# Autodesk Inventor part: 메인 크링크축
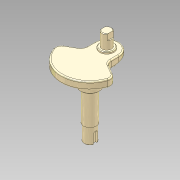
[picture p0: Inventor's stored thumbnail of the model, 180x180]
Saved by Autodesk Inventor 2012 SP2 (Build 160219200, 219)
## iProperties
Manager: KYOUNG IL JANG
Company: 한국ATC센터
Created: 2012-10
Part Number: 메인 크링크축
Document SubType Name: Modeling
Density: 1 g/cm^3
Checked By: KYOUNG IL JANG
Vendor: CBT Solutions
Designer: KYOUNG IL JANG
Material: 기본값
크링크폭: 19.000 mm
크랭크길이: 18.000 mm
크랭키위치: 65.000 mm
무게추: 90.000 mm
크랭크각도높이: 21.000 mm
크링크각도: -15.00 deg
Author: KYOUNG IL JANG
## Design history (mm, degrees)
sketch "스케치1"
  geometry: L1 (-19, 109.368)-(-19, 91.368); L2 (-19, 91.368)-(-44.545, 76.619); L3 (19, 109.368)-(19, 91.368); L4 (19, 91.368)-(44.545, 76.619); C1 r 32.5 at (0, 83) reference; C2 r 10 at (0, 83); C3 r 17.5 at (0, 83); A1 r 45 centre (0, 83) between (-44.545, 76.619) and (44.545, 76.619); A2 r 32.5 centre (0, 83) between (-19, 109.368) and (19, 109.368); A3 r 19 centre (0, 109.368) between (19, 109.368) and (-19, 109.368); 1 further point
  constraints: 8 end point, 6 point on circle, 5 centre point, 4 coincident, 2 equal length, 2 vertical alignment, 1 horizontal alignment, 1 parallel, 1 tangent, 1 vertical, 3 other
  dimensions: "d0" = 20 diameter of C2; "d1" = 35 diameter of C3; "d4" = 120 deg angle of L3 L4
  node "참조1"
extrude "돌출1" new body sketch "스케치1" distance "d7" = 12; taper "d8" = 0 deg
extrude "돌출2" join sketch "스케치1" distance "d9" = 5; taper "d10" = 0 deg
extrude "돌출3" join sketch "스케치1" distance "d11" = 100; taper "d12" = 0 deg
sketch "스케치2"
  geometry: C1 r 7.5 at (0, 109.368); C2 r 11 at (0, 109.368); A1 r 19 centre (0, 109.368) between (19, 109.368) and (-19, 109.368) reference; 1 further point
  constraints: 2 centre point, 2 coincident
  dimensions: "d13" = 15 diameter of C1; "d14" = 22 diameter of C2
extrude "돌출4" join sketch "스케치2" distance "d15" = 3; taper "d16" = 0 deg
extrude "돌출5" join sketch "스케치2" distance "d17" = 25; taper "d18" = 0 deg
node "작업 평면1"
sketch "스케치3"
  geometry: L1 (-5.75, 4.815)-(-5.75, -4.815); L2 (5.75, 4.815)-(5.75, -4.815); A1 r 7.5 centre (0, 0) between (-5.75, 4.815) and (-5.75, -4.815) reference; 1 further point
  constraints: 4 end point, 4 point on circle, 2 parallel, 1 vertical
  dimensions: "d20" = 11.5 distance between parallel lines of L2 L1
extrude "돌출6" cut sketch "스케치3" stored distance "d21" = 10; taper "d22" = 0 deg
sketch "스케치4"
  geometry: L1 (-19, 91.368)-(-19, 109.368) reference; L2 (19, 109.368)-(19, 91.368) reference; C1 r 17.5 at (0, 83) reference; 3 further points
  constraints: 2 point on line, 1 horizontal alignment, 1 other
node "작업 평면2"
  node "작업축1"
sketch "스케치5"
  geometry: L1 (0, 0)-(38, 0); L2 (38, 0)-(38, 50); L3 (38, 50)-(0, 50); L4 (0, 50)-(0, 0); L5 (38, 5.185)-(38, -12.202) reference; 2 further points
  constraints: 8 end point, 1 coincident, 1 collinear, 1 horizontal, 1 perpendicular
  dimensions: "d27" = 50 distance between parallel lines of L3 L1
extrude "돌출7" cut sketch "스케치5" stored distance "d28" = 10; taper "d29" = 0 deg
fillet "모깎기1" dims "d23" = 10, "d24" = 2
sketch "스케치6"
  geometry: C1 r 17.5 at (0, 0) reference; C2 r 15 at (0, 0); 1 further point
  constraints: 1 centre point, 1 coincident
  dimensions: "d30" = 30 diameter of C2
extrude "돌출8" join sketch "스케치6" distance "d31" = 21; taper "d32" = 0 deg
sketch "스케치7"
  geometry: C1 r 10 at (0, 0) reference; C2 r 9 at (0, 0); 1 further point
  constraints: 1 centre point, 1 coincident
  dimensions: "d33" = 1 radial gap between concentric circles of C1 C2
extrude "돌출9" cut sketch "스케치7" distance "d34" = 25; taper "d35" = 0 deg
node "작업 평면3"
sketch "스케치8"
  geometry: L1 (-9, 0)-(9, 0) reference; L2 (-3, 0)-(-3, 15); L3 (3, 15)-(3, 0); A1 r 3 centre (0, 15) between (3, 15) and (-3, 15); 2 further points
  constraints: 4 end point, 2 perpendicular, 2 point on circle, 2 point on line, 2 tangent, 1 centre point, 1 midpoint, 1 vertical alignment
  dimensions: "d36" = 6 distance between parallel lines of L3 L2; "d37" = 18 dimension on A1 L1
extrude "돌출10" cut sketch "스케치8" distance "d38" = 3.5; taper "d39" = 0 deg
chamfer "모따기1" distance "d40" = 1; stored, may be unused: second distance "d41" = 2, angle "d42" = 45 deg
node "솔리드1"
node "투영된 루프1"
other parameters: "d19" = 13
